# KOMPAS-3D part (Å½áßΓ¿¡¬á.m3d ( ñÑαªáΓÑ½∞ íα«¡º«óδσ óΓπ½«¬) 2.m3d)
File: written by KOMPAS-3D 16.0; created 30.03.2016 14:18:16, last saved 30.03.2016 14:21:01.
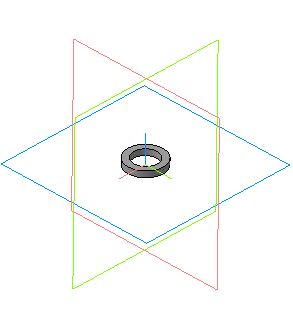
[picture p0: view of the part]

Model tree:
1. Эскиз:1
2. Операция выдавливания:1
     Расстояние 1 = 2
